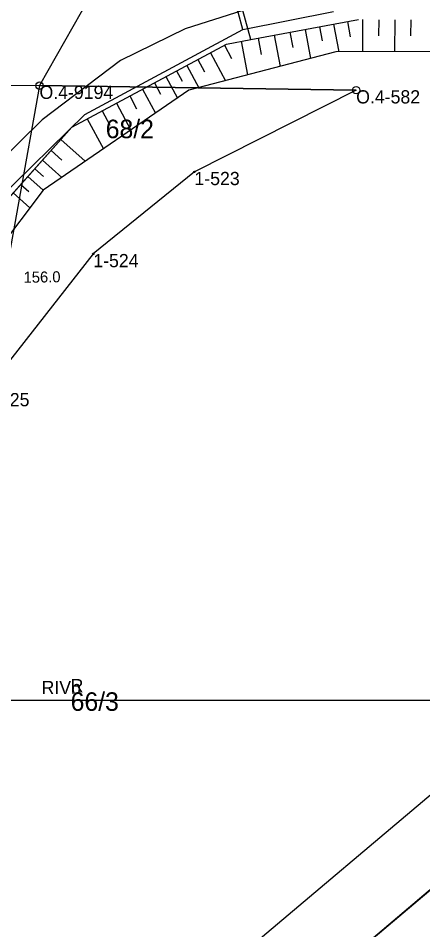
# Model space of a CAD drawing. Extents: x 5598798 to 5599616, y 5661498 to 5662453.
# Drawn here: x 5599219.7 to 5599247.3, y 5661984.4 to 5662046.3 of the extents above; entities that cross this region are included whole.
import ezdxf

# ---------------------------------------------------------------- set-up
doc = ezdxf.new("R2010")
doc.units = 0
for name, color, linetype in [('BUBZ_L_1', 7, 'Continuous'), ('Dzialki', 7, 'Continuous'), ('Kontury', 7, 'Continuous'), ('KTJZ_L_0', 7, 'Continuous'), ('Numery_dzialek', 7, 'Continuous'), ('Numery_konturow', 7, 'Continuous'), ('Numery_punktow', 7, 'Continuous'), ('Numery_uzytkow', 7, 'Continuous'), ('Podzial_sekcyjny_podstawowy', 7, 'Continuous'), ('Punkty', 7, 'Continuous'), ('RTPW_T_0', 7, 'Continuous'), ('SUOE_L_1', 7, 'Continuous'), ('SUPE_L_3', 7, 'Continuous'), ('Uzytki', 7, 'Continuous')]:
    doc.layers.add(name, color=color, linetype=linetype)

# ---------------------------------------------------------------- blocks, each defined once
blk = doc.blocks.new('GRT')
blk.add_circle((0, 0), 0.25)
blk = doc.blocks.new('GRO')
blk.add_circle((0, 0), 0.045)

msp = doc.modelspace()

# ---------------------------------------------------------------- linework, layer by layer
at = {"layer": 'BUBZ_L_1'}
for p, q in [((5599235.551757, 5662044.89372), (5599242.86973, 5662046.255203)), ((5599241.18233, 5662045.941269), (5599241.533489, 5662044.053785)), ((5599242.126072, 5662046.116849), (5599242.31767, 5662045.087006)), ((5599243.160816, 5662046.252856), (5599243.143127, 5662044.059357)), ((5599244.257565, 5662046.244011), (5599244.248772, 5662045.153583)), ((5599245.347994, 5662046.235218), (5599245.330508, 5662044.06693)), ((5599246.432138, 5662046.226475), (5599246.423445, 5662045.148579)), ((5599238.21463, 5662045.389139), (5599238.405385, 5662044.363832)), ((5599239.239937, 5662045.579893), (5599239.607863, 5662043.602294)), ((5599240.228737, 5662045.763856), (5599240.406149, 5662044.810263)), ((5599233.895112, 5662044.585507), (5599235.551757, 5662044.89372)), ((5599234.90594, 5662044.773568), (5599235.331285, 5662042.487338)), ((5599236.049055, 5662044.986241), (5599236.254156, 5662043.883827)), ((5599237.151469, 5662045.191341), (5599237.547064, 5662043.065018)), ((5599223.373416, 5662038.93789), (5599233.895112, 5662044.585507)), ((5599241.337013, 5662044.053104), (5599231.331598, 5662041.444571)), ((5599233.755877, 5662044.510772), (5599234.236256, 5662043.615811)), ((5599263.665708, 5662044.130407), (5599241.337013, 5662044.053104)), ((5599231.954015, 5662043.543605), (5599232.409993, 5662042.694103)), ((5599232.803517, 5662043.999584), (5599233.825893, 5662042.094864)), ((5599231.196261, 5662043.136874), (5599232.009724, 5662041.621366)), ((5599229.776593, 5662042.374854), (5599230.559925, 5662040.91548)), ((5599230.50628, 5662042.76652), (5599230.876634, 5662042.076539)), ((5599229.004915, 5662041.960649), (5599229.41912, 5662041.188971)), ((5599231.331598, 5662041.444571), (5599221.431197, 5662034.656453)), ((5599227.325783, 5662041.059359), (5599227.789032, 5662040.196312)), ((5599228.188831, 5662041.522608), (5599229.064913, 5662039.890439)), ((5599226.413071, 5662040.569453), (5599227.392885, 5662038.744028)), ((5599225.447836, 5662040.051354), (5599225.965935, 5662039.086119)), ((5599224.427055, 5662039.50344), (5599225.522882, 5662037.461879)), ((5599215.891937, 5662030.548676), (5599223.373416, 5662038.93789)), ((5599223.370299, 5662038.934394), (5599223.390074, 5662038.916758)), ((5599222.628251, 5662038.102313), (5599224.292413, 5662036.618219)), ((5599221.967572, 5662037.361473), (5599222.708412, 5662036.700793)), ((5599221.379338, 5662036.701868), (5599222.698548, 5662035.5254)), ((5599220.855605, 5662036.114591), (5599221.442883, 5662035.590859)), ((5599220.389302, 5662035.59171), (5599221.435063, 5662034.659104)), ((5599219.903712, 5662035.047203), (5599220.448219, 5662034.561613)), ((5599221.431197, 5662034.656453), (5599217.701626, 5662029.719398)), ((5599219.397499, 5662034.47957), (5599220.532764, 5662033.467144))]:
    msp.add_line(p, q, dxfattribs=at)
at = {"layer": 'Dzialki'}
for p, q in [((5599241.09, 5662076.83), (5599221.18, 5662041.76)), ((5599201.18, 5662042.06), (5599221.18, 5662041.76)), ((5599221.18, 5662041.76), (5599217.42, 5662020.87)), ((5599242.72, 5662041.45), (5599221.18, 5662041.76)), ((5599242.72, 5662041.45), (5599231.72, 5662035.9)), ((5599231.72, 5662035.9), (5599224.84, 5662030.32)), ((5599224.84, 5662030.32), (5599217.42, 5662020.87)), ((5599207.78, 5661959.89), (5599289.91, 5662029.05)), ((5599207.13, 5661952.92), (5599291.05, 5662023.52))]:
    msp.add_line(p, q, dxfattribs=at)
at = {"layer": 'Kontury'}
for p, q in [((5599242.72, 5662041.45), (5599231.72, 5662035.9)), ((5599231.72, 5662035.9), (5599224.84, 5662030.32)), ((5599224.84, 5662030.32), (5599217.42, 5662020.87)), ((5599207.78, 5661959.89), (5599289.91, 5662029.05)), ((5599291.05, 5662023.52), (5599207.13, 5661952.92))]:
    msp.add_line(p, q, dxfattribs=at)
at = {"layer": 'KTJZ_L_0'}
for p, q in [((5599235, 5662046.87), (5599231.08, 5662045.62)), ((5599235.55, 5662044.89), (5599235, 5662046.87)), ((5599231.08, 5662045.62), (5599226.7, 5662043.46)), ((5599233.9, 5662044.59), (5599235.55, 5662044.89)), ((5599223.37, 5662038.94), (5599233.9, 5662044.59)), ((5599226.7, 5662043.46), (5599221.36, 5662039.44)), ((5599221.36, 5662039.44), (5599215.67, 5662033.84)), ((5599215.89, 5662030.55), (5599223.37, 5662038.94))]:
    msp.add_line(p, q, dxfattribs=at)
at = {"layer": 'Podzial_sekcyjny_podstawowy'}
msp.add_line((5599200, 5662000), (5599600, 5662000), dxfattribs=at)
at = {"layer": 'SUOE_L_1'}
msp.add_line((5599235.009357, 5662045.580071), (5599232.376942, 5662055.314856), dxfattribs=at)
msp.add_line((5599235.009357, 5662045.580071), (5599232.376942, 5662055.314856), dxfattribs=at)
at = {"layer": 'SUPE_L_3'}
for p, q in [((5599235.009357, 5662045.580071), (5599232.376942, 5662055.314856)), ((5599235.009357, 5662045.580071), (5599241.174509, 5662046.800708)), ((5599224.255584, 5662039.803043), (5599235.009357, 5662045.580071)), ((5599218.324532, 5662034.005569), (5599224.255584, 5662039.803043))]:
    msp.add_line(p, q, dxfattribs=at)
at = {"layer": 'Uzytki'}
for p, q in [((5599201.18, 5662042.06), (5599221.18, 5662041.76)), ((5599221.18, 5662041.76), (5599242.72, 5662041.45)), ((5599242.72, 5662041.45), (5599231.72, 5662035.9)), ((5599231.72, 5662035.9), (5599224.84, 5662030.32)), ((5599224.84, 5662030.32), (5599217.42, 5662020.87)), ((5599207.78, 5661959.89), (5599289.91, 5662029.05)), ((5599291.05, 5662023.52), (5599207.13, 5661952.92))]:
    msp.add_line(p, q, dxfattribs=at)

# ---------------------------------------------------------------- block references
at = {"layer": 'Punkty'}
for name, p in [('GRT', (5599221.18, 5662041.76)), ('GRT', (5599242.72, 5662041.45)), ('GRO', (5599231.72, 5662035.9)), ('GRO', (5599224.84, 5662030.32))]:
    msp.add_blockref(name, p, dxfattribs=at)

# ---------------------------------------------------------------- texts
at = {"layer": 'Numery_dzialek'}
for s, p in [('68/2', (5599225.684573, 5662038.190012)), ('66/3', (5599223.298734, 5661999.2719))]:
    msp.add_text(s, height=1.26, dxfattribs=at).set_placement(p)
at = {"layer": 'Numery_konturow'}
msp.add_text('RIVb', height=0.9, dxfattribs=at).set_placement((5599221.321717, 5662000.407489))
at = {"layer": 'Numery_punktow'}
for s, p in [('O.4-9194', (5599221.18, 5662040.86)), ('O.4-582', (5599242.72, 5662040.55)), ('1-523', (5599231.72, 5662035)), ('1-524', (5599224.84, 5662029.42)), ('1-525', (5599217.42, 5662019.97))]:
    msp.add_text(s, height=0.9, dxfattribs=at).set_placement(p)
at = {"layer": 'Numery_uzytkow'}
msp.add_text('R', height=0.9, dxfattribs=at).set_placement((5599223.298734, 5662000.5319))
at = {"layer": 'RTPW_T_0'}
msp.add_text('156.0', height=0.75, rotation=0.830322, dxfattribs=at).set_placement((5599220.103407, 5662028.362))

doc.saveas('drawing.dxf')
